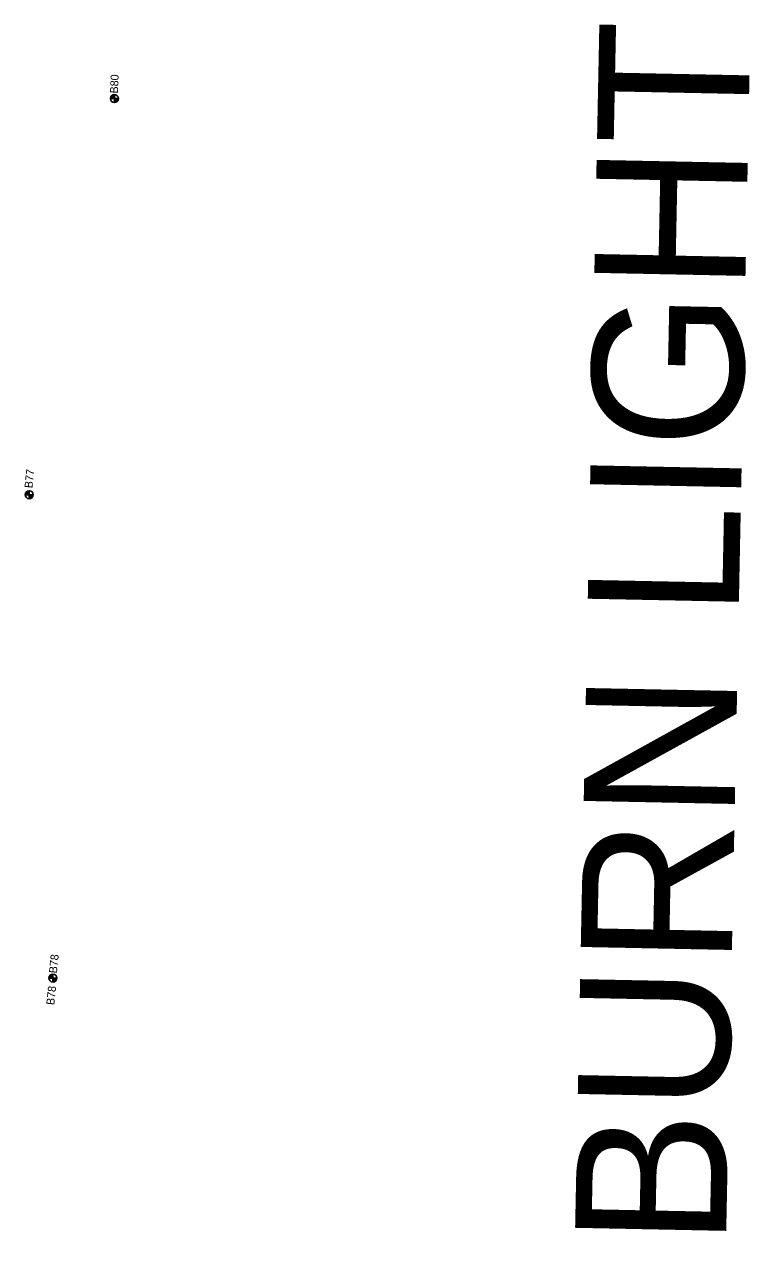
# Model space of a CAD drawing. Extents: x 345549 to 379569, y 127949 to 230467.
# Drawn here: x 360017 to 360923, y 172696 to 174228 of the extents above; entities that cross this region are included whole.
import ezdxf

# ---------------------------------------------------------------- set-up
doc = ezdxf.new("R2010")
doc.units = 0
for name, color, linetype in [('E_SOIL_BORE1 [KAPUR_CADDS_LEVELS]', 7, 'Continuous'), ('E_SOIL_BORE2 [KAPUR_CADDS_LEVELS]', 7, 'Continuous'), ('P_MARK', 7, 'Continuous'), ('P_TC_Text', 7, 'Continuous')]:
    doc.layers.add(name, color=color, linetype=linetype)

msp = doc.modelspace()

# ---------------------------------------------------------------- linework, layer by layer
at = {"layer": 'P_MARK'}
for p, q in [((360124, 174136), (360134, 174136)), ((360129, 174141), (360129, 174131)), ((360017.5, 173640.8), (360027.5, 173640.8)), ((360022.5, 173645.8), (360022.5, 173635.8)), ((360052.1, 173041.8), (360052.1, 173031.8)), ((360047.1, 173036.8), (360057.1, 173036.8))]:
    msp.add_line(p, q, dxfattribs=at)
for centre in [(360129, 174136), (360022.5, 173640.8), (360052.1, 173036.8)]:
    msp.add_circle(centre, 5, dxfattribs=at)
for centre, radius, start, end in [((360129, 174136), 4.5, 89.9869, 179.9869), ((360129, 174136), 4, 89.9869, 179.9869), ((360129, 174136), 3.5, 89.9869, 179.9869), ((360129, 174136), 3, 89.9869, 179.9869), ((360129, 174136), 2.5, 89.9869, 179.9869), ((360129, 174136), 2, 89.9869, 179.9869), ((360129, 174136), 1.5, 89.9869, 179.9869), ((360129, 174136), 1, 89.9869, 179.9869), ((360129, 174136), 0.5, 89.9869, 179.9869), ((360129, 174136), 4.5, 269.9869, 359.9869), ((360129, 174136), 4, 269.9869, 359.9869), ((360129, 174136), 3.5, 269.9869, 359.9869), ((360129, 174136), 3, 269.9869, 359.9869), ((360129, 174136), 2.5, 269.9869, 359.9869), ((360129, 174136), 2, 269.9869, 359.9869), ((360129, 174136), 1.5, 269.9869, 359.9869), ((360129, 174136), 1, 269.9869, 359.9869), ((360129, 174136), 0.5, 269.9869, 359.9869), ((360022.5, 173640.8), 4.5, 89.9869, 179.9869), ((360022.5, 173640.8), 4, 89.9869, 179.9869), ((360022.5, 173640.8), 3.5, 89.9869, 179.9869), ((360022.5, 173640.8), 3, 89.9869, 179.9869), ((360022.5, 173640.8), 2.5, 89.9869, 179.9869), ((360022.5, 173640.8), 2, 89.9869, 179.9869), ((360022.5, 173640.8), 1.5, 89.9869, 179.9869), ((360022.5, 173640.8), 1, 89.9869, 179.9869), ((360022.5, 173640.8), 0.5, 89.9869, 179.9869), ((360022.5, 173640.8), 4.5, 269.9869, 359.9869), ((360022.5, 173640.8), 4, 269.9869, 359.9869), ((360022.5, 173640.8), 3.5, 269.9869, 359.9869), ((360022.5, 173640.8), 3, 269.9869, 359.9869), ((360022.5, 173640.8), 2.5, 269.9869, 359.9869), ((360022.5, 173640.8), 2, 269.9869, 359.9869), ((360022.5, 173640.8), 1.5, 269.9869, 359.9869), ((360022.5, 173640.8), 1, 269.9869, 359.9869), ((360022.5, 173640.8), 0.5, 269.9869, 359.9869), ((360052.1, 173036.8), 4.5, 89.9869, 179.9869), ((360052.1, 173036.8), 4, 89.9869, 179.9869), ((360052.1, 173036.8), 3.5, 89.9869, 179.9869), ((360052.1, 173036.8), 3, 89.9869, 179.9869), ((360052.1, 173036.8), 2.5, 89.9869, 179.9869), ((360052.1, 173036.8), 2, 89.9869, 179.9869), ((360052.1, 173036.8), 1.5, 89.9869, 179.9869), ((360052.1, 173036.8), 1, 89.9869, 179.9869), ((360052.1, 173036.8), 0.5, 89.9869, 179.9869), ((360052.1, 173036.8), 4.5, 269.9869, 359.9869), ((360052.1, 173036.8), 4, 269.9869, 359.9869), ((360052.1, 173036.8), 3.5, 269.9869, 359.9869), ((360052.1, 173036.8), 3, 269.9869, 359.9869), ((360052.1, 173036.8), 2.5, 269.9869, 359.9869), ((360052.1, 173036.8), 2, 269.9869, 359.9869), ((360052.1, 173036.8), 1.5, 269.9869, 359.9869), ((360052.1, 173036.8), 1, 269.9869, 359.9869), ((360052.1, 173036.8), 0.5, 269.9869, 359.9869)]:
    msp.add_arc(centre, radius, start, end, dxfattribs=at)

# ---------------------------------------------------------------- texts
at = {"layer": 'E_SOIL_BORE1 [KAPUR_CADDS_LEVELS]'}
for s, rotation, p in [('B80', 87.2646, (360133.4, 174142.1)), ('B77', 84.1728, (360026.5, 173648.6)), ('B78', 84.1728, (360057.1, 173042.3))]:
    msp.add_text(s, height=10, rotation=rotation, dxfattribs=at).set_placement(p)
at = {"layer": 'E_SOIL_BORE2 [KAPUR_CADDS_LEVELS]'}
msp.add_text('B78', height=10, rotation=84.1728, dxfattribs=at).set_placement((360053.8, 173002.7))
at = {"layer": 'P_TC_Text'}
msp.add_text('TRAFFIC CONTROL DRUM WITH TYPE C STEADY BURN LIGHT', height=189, rotation=88.8462, dxfattribs=at).set_placement((360771.8, 166649.6))

doc.saveas('drawing.dxf')
